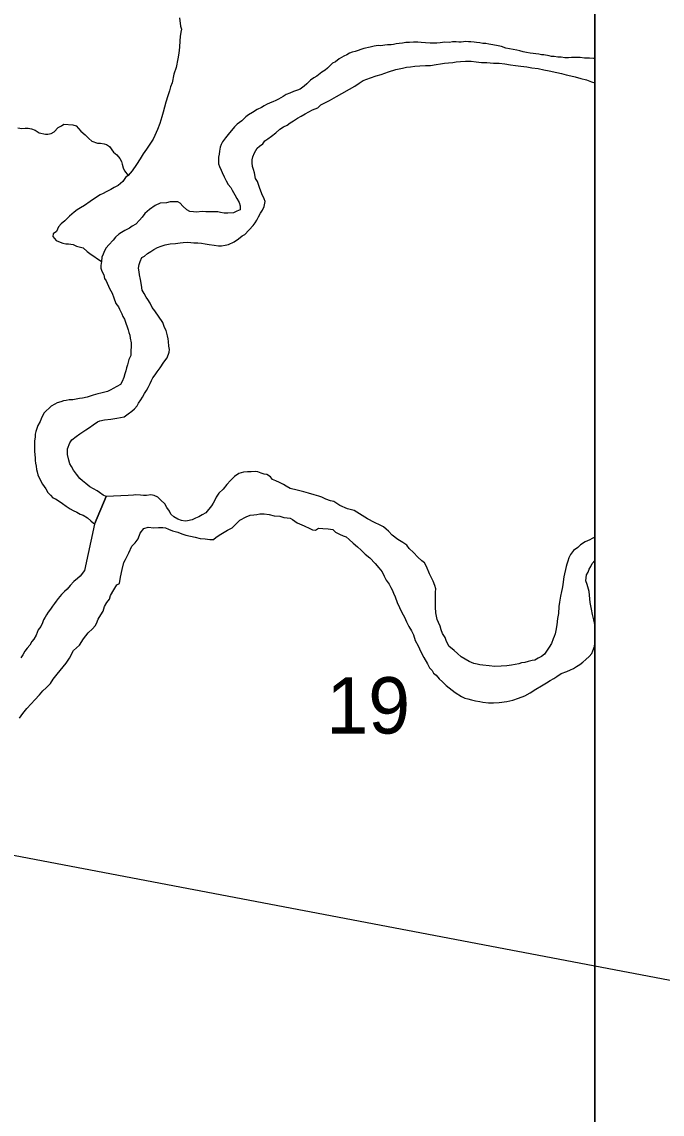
# Model space of a CAD drawing. Extents: x -17 to 88, y -5 to 22.
# Drawn here: x 8.974 to 9.45, y 16.322 to 17.134 of the extents above; entities that cross this region are included whole.
import ezdxf

# ---------------------------------------------------------------- set-up
doc = ezdxf.new("R2010")
doc.units = 0
for name, color, linetype in [('GM_X_Major_River', 7, 'Continuous'), ('GM_X_Minor_River', 7, 'Continuous'), ('GM_X_Section', 7, 'Continuous'), ('GM_X_Section_Text', 7, 'Continuous'), ('GM_X_Township', 7, 'Continuous'), ('SH_Data', 7, 'Continuous'), ('TX_P_10', 7, 'Continuous')]:
    doc.layers.add(name, color=color, linetype=linetype)

msp = doc.modelspace()

# ---------------------------------------------------------------- linework, layer by layer
at = {"layer": 'GM_X_Major_River'}
msp.add_line((9.03704, 16.7812), (9.02835, 16.76067), dxfattribs=at)
for points in [[(9.28947, 16.67417), (9.28875, 16.67647), (9.28691, 16.67954), (9.28582, 16.68222), (9.2851, 16.68489), (9.28401, 16.68757), (9.28292, 16.68987), (9.28187, 16.69482), (9.28157, 16.69901), (9.28161, 16.70128), (9.28167, 16.70432), (9.28172, 16.70736), (9.28177, 16.71001), (9.28182, 16.71267), (9.2811, 16.71496), (9.28003, 16.7184), (9.27892, 16.72032), (9.27709, 16.72377), (9.2749, 16.72913), (9.27343, 16.73181), (9.27156, 16.73337), (9.26857, 16.73608), (9.26521, 16.73956), (9.26223, 16.74266), (9.26037, 16.74497), (9.25737, 16.74692), (9.25361, 16.74927), (9.24948, 16.75239), (9.24688, 16.75547), (9.24501, 16.75702), (9.24314, 16.75858), (9.2405, 16.75977), (9.23635, 16.76174), (9.23108, 16.7645), (9.22131, 16.77076), (9.21639, 16.77199), (9.21073, 16.77437), (9.20623, 16.77749), (9.20358, 16.77792), (9.20017, 16.77912), (9.19716, 16.7807), (9.1949, 16.7815), (9.19149, 16.78232), (9.18733, 16.78354), (9.18393, 16.78474), (9.17901, 16.78597), (9.17371, 16.78721), (9.1707, 16.78878), (9.16882, 16.78996), (9.16581, 16.79153), (9.16317, 16.79272), (9.16053, 16.79391), (9.15904, 16.79584), (9.15641, 16.7974), (9.15452, 16.79782), (9.15225, 16.79862), (9.1496, 16.79943), (9.14771, 16.79984), (9.14466, 16.79952), (9.142, 16.79957), (9.13896, 16.79925), (9.13551, 16.79817), (9.13243, 16.79595), (9.12933, 16.79297), (9.12662, 16.78998), (9.12389, 16.78661), (9.12079, 16.78363), (9.11884, 16.78063), (9.11766, 16.77838), (9.11647, 16.77612), (9.1153, 16.77424), (9.11102, 16.769), (9.10833, 16.76754), (9.10602, 16.76606), (9.10334, 16.76497), (9.10103, 16.76388), (9.0976, 16.76318), (9.09569, 16.76283), (9.09304, 16.76326), (9.0904, 16.76445), (9.08739, 16.76603), (9.08514, 16.76797), (9.08404, 16.77027), (9.08219, 16.77296), (9.08072, 16.77564), (9.07773, 16.77836), (9.07549, 16.78068), (9.07285, 16.78187), (9.0702, 16.7823), (9.06715, 16.78197), (9.06487, 16.78201), (9.06259, 16.78206), (9.05918, 16.7825), (9.05727, 16.78215), (9.05346, 16.78184), (9.03704, 16.7812)], [(9.04902, 16.72687), (9.05025, 16.73216), (9.05144, 16.73442), (9.05381, 16.73931), (9.05618, 16.7442), (9.05851, 16.74681), (9.06085, 16.74981), (9.06245, 16.75396), (9.06517, 16.75732), (9.06824, 16.75841), (9.07241, 16.75795), (9.07584, 16.75827), (9.07926, 16.7582), (9.08115, 16.75779), (9.08342, 16.75699), (9.08644, 16.75579), (9.09021, 16.75458), (9.09324, 16.75339), (9.09626, 16.75257), (9.09967, 16.75175), (9.10307, 16.75092), (9.10686, 16.75009), (9.11066, 16.74964), (9.11407, 16.7492), (9.11673, 16.74915), (9.11867, 16.75102), (9.12213, 16.75323), (9.12713, 16.75617), (9.13058, 16.75801), (9.13329, 16.76062), (9.13639, 16.7636), (9.141, 16.76617), (9.14406, 16.76725), (9.14673, 16.76758), (9.14902, 16.76792), (9.15131, 16.76826), (9.15435, 16.7682), (9.15814, 16.76775), (9.16193, 16.76692), (9.1661, 16.76646), (9.16913, 16.76565), (9.1714, 16.76523), (9.17368, 16.76518), (9.17556, 16.76401), (9.17894, 16.76167), (9.18422, 16.75929), (9.18836, 16.75732), (9.19025, 16.75652), (9.19252, 16.7561), (9.19483, 16.75758), (9.19787, 16.75752), (9.20204, 16.75706), (9.20546, 16.75662), (9.20732, 16.75469), (9.21034, 16.75311), (9.21298, 16.75192), (9.21524, 16.75112), (9.21749, 16.74918), (9.22048, 16.74647), (9.22385, 16.74375), (9.22647, 16.74142), (9.22945, 16.73833), (9.23282, 16.73561), (9.23692, 16.73135), (9.23953, 16.72827), (9.24213, 16.72518), (9.2436, 16.72212), (9.24506, 16.71905), (9.24728, 16.71597), (9.24838, 16.71367), (9.24949, 16.71175), (9.25058, 16.70945), (9.25167, 16.70677), (9.25312, 16.70257), (9.25495, 16.69874), (9.25678, 16.69491), (9.25861, 16.69146), (9.26007, 16.68801), (9.26191, 16.68456), (9.26375, 16.68149), (9.26521, 16.67842), (9.26666, 16.67422), (9.26886, 16.67038), (9.27068, 16.66579), (9.27288, 16.66157), (9.27584, 16.65696), (9.2773, 16.65389), (9.27917, 16.65196), (9.28027, 16.65004), (9.28214, 16.64849), (9.28437, 16.64579), (9.28699, 16.64346), (9.2896, 16.64076), (9.29635, 16.6357), (9.30086, 16.63257), (9.3035, 16.63138), (9.30577, 16.63096), (9.30842, 16.63015), (9.31144, 16.62934), (9.31448, 16.6289), (9.31675, 16.62848)], [(9.02835, 16.76067), (9.02087, 16.72625), (9.01775, 16.72213), (9.01581, 16.72027), (9.01311, 16.71804), (9.01039, 16.71505), (9.00806, 16.71244), (9.00613, 16.71057), (9.0038, 16.70834), (9.00146, 16.70534), (8.99991, 16.70347), (8.99873, 16.7016), (8.99718, 16.69973), (8.99562, 16.69748), (8.99405, 16.69523), (8.99288, 16.69335), (8.9917, 16.69147), (8.99053, 16.68959), (8.98972, 16.68733), (8.98853, 16.6847), (8.98658, 16.68208), (8.98499, 16.67831), (8.98342, 16.6753), (8.98186, 16.67343), (8.98029, 16.6708), (8.97835, 16.66856), (8.97678, 16.66631), (8.97521, 16.66368), (8.97365, 16.66143)], [(9.4, 16.75091), (9.3981, 16.75001), (9.39618, 16.7489), (9.39273, 16.74745), (9.38927, 16.74523), (9.38733, 16.74337), (9.38425, 16.74115), (9.38191, 16.73815), (9.38072, 16.73552), (9.37992, 16.73325), (9.37911, 16.73099), (9.3787, 16.7291), (9.37704, 16.72154), (9.37659, 16.71775), (9.37616, 16.71548), (9.37573, 16.71283), (9.37531, 16.71056), (9.37449, 16.70715), (9.37364, 16.70261), (9.37321, 16.69958), (9.37311, 16.69427), (9.37228, 16.69049), (9.37181, 16.68594), (9.37097, 16.68177), (9.37054, 16.67913), (9.36975, 16.67724), (9.36895, 16.67536), (9.36775, 16.67196), (9.36618, 16.66933), (9.36462, 16.66708), (9.36266, 16.66408), (9.36034, 16.66223), (9.35804, 16.66113), (9.35535, 16.65966), (9.35345, 16.65932), (9.35039, 16.65862), (9.3481, 16.6579), (9.34543, 16.65757), (9.34351, 16.65684), (9.34085, 16.65651), (9.33817, 16.6558), (9.33474, 16.65549), (9.33056, 16.65519), (9.32561, 16.6549), (9.32143, 16.65535), (9.31688, 16.65582), (9.31461, 16.65624), (9.31271, 16.65666), (9.31006, 16.65709), (9.30667, 16.65867), (9.30065, 16.6622), (9.29803, 16.66452), (9.29541, 16.66685), (9.29167, 16.66996), (9.28947, 16.67417)], [(8.97282, 16.61663), (8.97516, 16.62001), (8.97827, 16.62375), (8.98138, 16.62711), (8.98409, 16.63009), (8.98758, 16.63383), (8.98992, 16.63682), (8.99262, 16.63905), (8.99573, 16.64241), (8.99769, 16.64541), (9.0008, 16.64915), (9.00742, 16.65738), (9.00977, 16.66114), (9.01291, 16.66678), (9.01717, 16.67087), (9.0203, 16.67537), (9.0238, 16.67987), (9.0269, 16.68285), (9.02884, 16.68509), (9.03002, 16.68697), (9.03122, 16.68998), (9.03318, 16.69336), (9.03475, 16.69599), (9.03595, 16.69939), (9.03753, 16.70239), (9.03948, 16.70502), (9.04029, 16.70766), (9.04265, 16.71179), (9.045, 16.71555), (9.04692, 16.71665), (9.04777, 16.72119), (9.04902, 16.72687)], [(9.4, 16.68596), (9.39995, 16.68617), (9.39925, 16.68961), (9.39819, 16.69342), (9.3975, 16.69761), (9.39646, 16.70257), (9.39584, 16.71055), (9.39442, 16.7159), (9.39333, 16.71857), (9.3938, 16.72312), (9.39497, 16.725), (9.39577, 16.72726), (9.39695, 16.72914), (9.39813, 16.7314), (9.4, 16.73355)], [(9.31675, 16.62848), (9.32092, 16.62802), (9.32473, 16.62795), (9.32891, 16.62825), (9.33463, 16.62891), (9.33921, 16.62996), (9.34342, 16.6314), (9.34802, 16.63321), (9.35186, 16.63542), (9.35609, 16.638), (9.36032, 16.64058), (9.36416, 16.64279), (9.36686, 16.64464), (9.36955, 16.64611), (9.37185, 16.64758), (9.37494, 16.6498), (9.37915, 16.65124), (9.38183, 16.65234), (9.38413, 16.65343), (9.38644, 16.65491), (9.38875, 16.65638), (9.39107, 16.65824), (9.39338, 16.66009), (9.3957, 16.66233), (9.39765, 16.66457), (9.39844, 16.66645), (9.39964, 16.66985), (9.4, 16.67203)]]:
    msp.add_lwpolyline(points, dxfattribs=at)
at = {"layer": 'GM_X_Minor_River'}
msp.add_line((9.02835, 16.76067), (9.03704, 16.7812), dxfattribs=at)
for points in [[(9.09164, 17.13657), (9.09229, 17.13049), (9.093, 17.1282), (9.09258, 17.12593), (9.09214, 17.1229), (9.0917, 17.11949), (9.09162, 17.11493), (9.09115, 17.11038), (9.09031, 17.10622), (9.08905, 17.09979), (9.08744, 17.09488), (9.08618, 17.08845), (9.08498, 17.08543), (9.08417, 17.08241), (9.08296, 17.07864), (9.08135, 17.07411), (9.08052, 17.07033), (9.07931, 17.06655), (9.07848, 17.06315), (9.07687, 17.05824), (9.07527, 17.05372), (9.07328, 17.0492), (9.07209, 17.04656), (9.07053, 17.04431), (9.06896, 17.04206), (9.06701, 17.03906), (9.06466, 17.03569), (9.06231, 17.03193), (9.05957, 17.02781), (9.05644, 17.02293), (9.05334, 17.01957), (9.05141, 17.01808), (9.04945, 17.01508), (9.04597, 17.01211), (9.0429, 17.01065), (9.0406, 17.00917), (9.03714, 17.00734), (9.03484, 17.00624), (9.03254, 17.00514), (9.02907, 17.00293), (9.02522, 17.00034), (9.02099, 16.99738), (9.01791, 16.99554), (9.0156, 16.99406), (9.01328, 16.99221), (9.00981, 16.98924), (9.00632, 16.98588), (9.00362, 16.98365), (9.00167, 16.98141), (9.00009, 16.97802), (8.99777, 16.97617), (8.99736, 16.97427), (8.99996, 16.97119), (9.00298, 16.96999), (9.00487, 16.9692), (9.00714, 16.96878), (9.00904, 16.96874), (9.01246, 16.9683), (9.0151, 16.96711), (9.01812, 16.9663), (9.02002, 16.96588), (9.02301, 16.96317), (9.02488, 16.96161), (9.03352, 16.95576)], [(9.4, 17.10655), (9.39905, 17.10656), (9.39601, 17.10662), (9.39411, 17.10666), (9.39221, 17.10669), (9.38917, 17.10713), (9.38689, 17.10717), (9.38499, 17.10721), (9.38271, 17.10725), (9.38043, 17.10691), (9.37777, 17.10696), (9.37511, 17.10739), (9.37245, 17.10744), (9.3698, 17.10787), (9.3679, 17.1079), (9.366, 17.10832), (9.36222, 17.10915), (9.36032, 17.10918), (9.35842, 17.1096), (9.35615, 17.11002), (9.35425, 17.11006), (9.35198, 17.11048), (9.34932, 17.11091), (9.34667, 17.11134), (9.3444, 17.11214), (9.34213, 17.11256), (9.3338, 17.11423), (9.33078, 17.11543), (9.32813, 17.11586), (9.32434, 17.11669), (9.32131, 17.11712), (9.31903, 17.11754), (9.31675, 17.11759), (9.31448, 17.11801), (9.31221, 17.11843), (9.31031, 17.11847), (9.30803, 17.11889), (9.30613, 17.11892), (9.30423, 17.11896), (9.3008, 17.11864), (9.2989, 17.11868), (9.297, 17.11871), (9.29434, 17.11876), (9.29205, 17.11842), (9.28863, 17.11849), (9.28521, 17.11817), (9.28254, 17.11784), (9.28026, 17.11788), (9.2776, 17.11794), (9.27418, 17.118), (9.27114, 17.11843), (9.26848, 17.11848), (9.26544, 17.11854), (9.26239, 17.11822), (9.25973, 17.11827), (9.25707, 17.11794), (9.25478, 17.1176), (9.25249, 17.11726), (9.25058, 17.11692), (9.24867, 17.11657), (9.24601, 17.11662), (9.24411, 17.11628), (9.24106, 17.11595)], [(9.24106, 17.11595), (9.23916, 17.11599), (9.23611, 17.11567), (9.23306, 17.11496), (9.22847, 17.11391), (9.22618, 17.11319), (9.22426, 17.11247), (9.22197, 17.11175), (9.21968, 17.11103), (9.21776, 17.11031), (9.21584, 17.10921), (9.21354, 17.10811), (9.21008, 17.10628), (9.20738, 17.10405), (9.20508, 17.10295), (9.20314, 17.10109), (9.20158, 17.09922), (9.19966, 17.09774), (9.19735, 17.09626), (9.19349, 17.09329), (9.19119, 17.0922), (9.18887, 17.09034), (9.18616, 17.08774), (9.18423, 17.08587), (9.18114, 17.08365), (9.17923, 17.08293), (9.17617, 17.08184), (9.17349, 17.08075), (9.1708, 17.07967), (9.16849, 17.07819), (9.16504, 17.07635), (9.16312, 17.07525), (9.16082, 17.07415), (9.1589, 17.07343), (9.15622, 17.07234), (9.1543, 17.07124), (9.15238, 17.07013), (9.14931, 17.06867), (9.14584, 17.06646), (9.14277, 17.06462), (9.14084, 17.06313), (9.13774, 17.06015), (9.13427, 17.05756), (9.13234, 17.0557), (9.12767, 17.05009), (9.12572, 17.04746), (9.12338, 17.04447), (9.12258, 17.04258), (9.12179, 17.0407), (9.12135, 17.03767), (9.12093, 17.0354), (9.12051, 17.03313), (9.12045, 17.03009), (9.12042, 17.0282), (9.12114, 17.02628), (9.12261, 17.0236), (9.12334, 17.02168), (9.1248, 17.01862), (9.12626, 17.01556), (9.12773, 17.01287), (9.12959, 17.01056), (9.1307, 17.00864), (9.13253, 17.00518), (9.134, 17.0025), (9.13585, 16.99943), (9.13657, 16.99714), (9.13651, 16.9941), (9.13421, 16.993), (9.13153, 16.99191), (9.12734, 16.99161), (9.12468, 16.99166), (9.12202, 16.99209), (9.12013, 16.9925), (9.11633, 16.99258), (9.11291, 16.99264), (9.11101, 16.99267), (9.10835, 16.99272), (9.10416, 16.99242), (9.10188, 16.99246), (9.09922, 16.99289), (9.09697, 16.99407), (9.09398, 16.99679), (9.09212, 16.9991), (9.09023, 16.9999), (9.08719, 16.99995), (9.08453, 17), (9.08185, 16.99929), (9.07728, 16.99899), (9.07345, 16.99717), (9.06921, 16.99421), (9.06573, 16.99124), (9.06378, 16.98861), (9.06184, 16.98637), (9.05912, 16.98338), (9.05644, 16.98191), (9.05451, 16.98043), (9.05105, 16.9786), (9.04836, 16.97713), (9.04644, 16.97602), (9.04412, 16.97379), (9.04217, 16.97155)], [(9.13534, 16.97248), (9.13805, 16.9747), (9.13997, 16.97581), (9.14618, 16.98253), (9.14773, 16.9844), (9.14891, 16.98627), (9.1501, 16.98891), (9.15167, 16.99154), (9.15323, 16.99379), (9.15442, 16.99643), (9.15525, 17.00021), (9.15453, 17.00212), (9.1527, 17.00595), (9.15088, 17.01054), (9.15017, 17.01283), (9.14945, 17.01513), (9.14797, 17.01743), (9.14729, 17.02162), (9.14657, 17.02391), (9.14585, 17.0262), (9.14552, 17.02887), (9.14557, 17.03115), (9.14599, 17.03342), (9.14718, 17.03643), (9.14915, 17.03981), (9.15108, 17.0413), (9.15339, 17.04315), (9.15496, 17.0454), (9.15726, 17.04688), (9.15996, 17.04873), (9.16305, 17.05133), (9.16614, 17.05393), (9.16884, 17.05578), (9.17152, 17.05687), (9.17384, 17.05872), (9.17614, 17.0602), (9.17922, 17.06204), (9.18191, 17.06351), (9.18498, 17.06535), (9.18767, 17.06682), (9.19036, 17.06829), (9.19419, 17.06974), (9.19651, 17.07197), (9.19958, 17.07343), (9.20304, 17.07527), (9.20804, 17.07821), (9.22187, 17.08593), (9.22495, 17.08815), (9.22803, 17.08999), (9.23071, 17.09108), (9.23339, 17.09217), (9.2376, 17.09361), (9.24142, 17.09468), (9.24678, 17.09648), (9.25214, 17.09828), (9.2571, 17.09933), (9.26015, 17.10003), (9.2632, 17.10035), (9.26625, 17.10068), (9.27006, 17.10099), (9.27424, 17.10129), (9.27804, 17.10122), (9.28224, 17.1019), (9.28529, 17.1026), (9.28834, 17.10292), (9.29139, 17.10325), (9.29444, 17.10357), (9.29711, 17.1039), (9.30015, 17.10422), (9.30396, 17.10453), (9.30814, 17.10446), (9.31193, 17.10401), (9.31573, 17.10356), (9.31991, 17.10348), (9.32484, 17.10301), (9.32903, 17.10293), (9.3332, 17.10247), (9.33737, 17.10163), (9.34116, 17.10118), (9.34495, 17.10074), (9.34951, 17.10027), (9.35329, 17.09944), (9.35785, 17.09898), (9.36201, 17.09814), (9.36618, 17.0973), (9.37186, 17.09606), (9.37527, 17.09524), (9.37867, 17.09441), (9.38208, 17.09359), (9.38549, 17.09277), (9.38964, 17.09155), (9.39381, 17.09071), (9.39758, 17.08913), (9.4, 17.08827)], [(8.97149, 17.05488), (8.97452, 17.05445), (8.97681, 17.05478), (8.97909, 17.05474), (8.98174, 17.05431), (8.98438, 17.05312), (8.98739, 17.05117), (8.99194, 17.05033), (8.99384, 17.05029), (8.99612, 17.05063), (8.99843, 17.0521), (9.00153, 17.05508), (9.00384, 17.05656), (9.00576, 17.05766), (9.01221, 17.05716), (9.01486, 17.05636), (9.01821, 17.0525), (9.02158, 17.04978), (9.02419, 17.04707), (9.02644, 17.04513), (9.03059, 17.04353)], [(9.03059, 17.04353), (9.03287, 17.04349), (9.03553, 17.04306), (9.03742, 17.04265), (9.03967, 17.04109), (9.04263, 17.03685), (9.04488, 17.03491), (9.04711, 17.03221), (9.04859, 17.02991), (9.04893, 17.028), (9.04964, 17.02533), (9.05074, 17.02303), (9.05334, 17.01957)], [(9.04217, 16.97155), (9.03907, 16.96819), (9.03713, 16.96594), (9.03594, 16.96369), (9.03475, 16.96105), (9.03395, 16.95879), (9.03352, 16.95576), (9.03308, 16.95273), (9.03304, 16.95083), (9.03376, 16.94854), (9.03523, 16.94585), (9.03594, 16.94318), (9.03705, 16.94126), (9.0396, 16.93552), (9.04144, 16.93207), (9.04289, 16.92862), (9.04434, 16.92442), (9.04619, 16.92211), (9.04692, 16.92019), (9.04876, 16.91674), (9.04948, 16.91483), (9.05059, 16.91291), (9.05167, 16.90985), (9.05276, 16.90717), (9.05348, 16.90488), (9.05382, 16.90298), (9.05455, 16.90106), (9.05489, 16.89878), (9.05558, 16.89535), (9.05553, 16.89231), (9.05547, 16.88965), (9.0554, 16.88586), (9.05383, 16.88285), (9.05299, 16.87907), (9.05219, 16.87681), (9.05177, 16.87453), (9.05097, 16.87227), (9.05016, 16.86963), (9.04896, 16.86661), (9.04778, 16.86435), (9.04509, 16.86289), (9.0424, 16.86142), (9.04048, 16.86031), (9.03818, 16.85922), (9.03512, 16.85851), (9.03321, 16.85779), (9.03092, 16.85745), (9.02748, 16.85638), (9.02518, 16.85566), (9.02289, 16.85494), (9.01945, 16.85425), (9.01717, 16.85391), (9.01488, 16.85357), (9.0122, 16.85286), (9.00954, 16.85291), (9.00725, 16.85258), (9.00535, 16.85223), (9.00343, 16.85151), (9.00076, 16.8508), (8.99884, 16.84969), (8.99615, 16.84822), (8.99111, 16.84338), (8.98994, 16.8415), (8.98875, 16.83887), (8.98795, 16.83698), (8.98638, 16.83397), (8.98557, 16.83171), (8.98477, 16.82945), (8.98436, 16.82756), (8.98431, 16.82528), (8.98388, 16.82263), (8.98383, 16.81997), (8.98378, 16.81732), (8.98373, 16.81466), (8.98407, 16.81237), (8.9844, 16.80971), (8.98437, 16.80781), (8.98471, 16.80591), (8.98505, 16.80362), (8.98539, 16.80134), (8.98573, 16.79943), (8.98645, 16.79714), (8.98827, 16.79293), (8.98974, 16.79024), (8.99234, 16.78678), (8.99381, 16.78409), (8.99567, 16.78216), (8.99754, 16.78022), (8.99943, 16.77943), (9.00131, 16.77826), (9.00468, 16.77592), (9.00731, 16.77397), (9.01032, 16.77201), (9.01257, 16.77083), (9.01521, 16.76964), (9.01785, 16.76808), (9.02011, 16.76727), (9.02312, 16.76532), (9.02574, 16.76299), (9.02761, 16.76144), (9.02835, 16.76067)], [(9.03704, 16.7812), (9.03484, 16.78219), (9.03221, 16.78414), (9.03033, 16.78531), (9.0277, 16.78688), (9.02507, 16.78845), (9.02207, 16.79078), (9.01945, 16.79273), (9.01758, 16.79466), (9.01498, 16.79775), (9.01275, 16.80083), (9.01128, 16.80351), (9.01018, 16.80543), (9.00947, 16.8081), (9.0084, 16.8123), (9.00848, 16.81648), (9.01009, 16.821), (9.01165, 16.82325), (9.01474, 16.82585), (9.01744, 16.8277), (9.01975, 16.82918), (9.02206, 16.83066), (9.02475, 16.8325), (9.02745, 16.83435), (9.03053, 16.83657), (9.03245, 16.8373), (9.03588, 16.83799), (9.04046, 16.83867), (9.04503, 16.83934), (9.05037, 16.84038), (9.05346, 16.8426), (9.05615, 16.84445), (9.05809, 16.84631), (9.06003, 16.84856), (9.06121, 16.85043), (9.06278, 16.85306), (9.06395, 16.85494), (9.06552, 16.85757), (9.06709, 16.85982), (9.06827, 16.86208), (9.06984, 16.86509), (9.07065, 16.86735), (9.07182, 16.86923), (9.07339, 16.87148), (9.07495, 16.87372), (9.07729, 16.87672), (9.08003, 16.88084), (9.08237, 16.88422), (9.08397, 16.88837), (9.084, 16.89027), (9.08367, 16.89293), (9.08335, 16.89635), (9.08301, 16.89826), (9.08267, 16.90054), (9.0816, 16.90436), (9.08051, 16.90666), (9.07906, 16.91048), (9.07313, 16.91895), (9.07128, 16.92164), (9.06982, 16.9247), (9.06796, 16.9274), (9.06686, 16.92932), (9.06539, 16.932), (9.06391, 16.93431), (9.06322, 16.93812), (9.06254, 16.94231), (9.06184, 16.94574), (9.06151, 16.94802), (9.06118, 16.95069), (9.0616, 16.95334), (9.06241, 16.9556), (9.06361, 16.95862), (9.06553, 16.95972), (9.06784, 16.96158), (9.07015, 16.96305), (9.07246, 16.96453), (9.07515, 16.966), (9.07783, 16.96709), (9.08089, 16.96817), (9.08471, 16.96886), (9.08852, 16.96917), (9.09194, 16.96948), (9.09423, 16.96982), (9.09766, 16.97014), (9.09993, 16.96972), (9.10221, 16.96967), (9.10525, 16.96962), (9.10791, 16.96919), (9.11056, 16.96876), (9.1136, 16.96832), (9.11739, 16.96787), (9.12042, 16.96744), (9.1227, 16.96739), (9.12537, 16.96773), (9.12805, 16.96843), (9.13226, 16.97025), (9.13534, 16.97248)]]:
    msp.add_lwpolyline(points, dxfattribs=at)
at = {"layer": 'GM_X_Section'}
msp.add_line((9.4, 16.13558), (9.4, 17.13596), dxfattribs=at)
at = {"layer": 'GM_X_Township'}
msp.add_lwpolyline([(8.70899, 14.1), (9.4, 14.1), (9.4, 20.16689)], dxfattribs=at)
at = {"layer": 'SH_Data'}
msp.add_line((9.4, 20.9), (9.4, 14.1), dxfattribs=at)
at = {"layer": 'TX_P_10'}
msp.add_lwpolyline([(5.97365, 17.08476), (9.824, 16.35201), (9.824, 15.77473)], close=True, dxfattribs=at)

# ---------------------------------------------------------------- texts
at = {"layer": 'GM_X_Section_Text'}
msp.add_text('19', height=0.041856, rotation=0.00001, dxfattribs=at).set_placement((9.20056, 16.60514))

doc.saveas('drawing.dxf')
